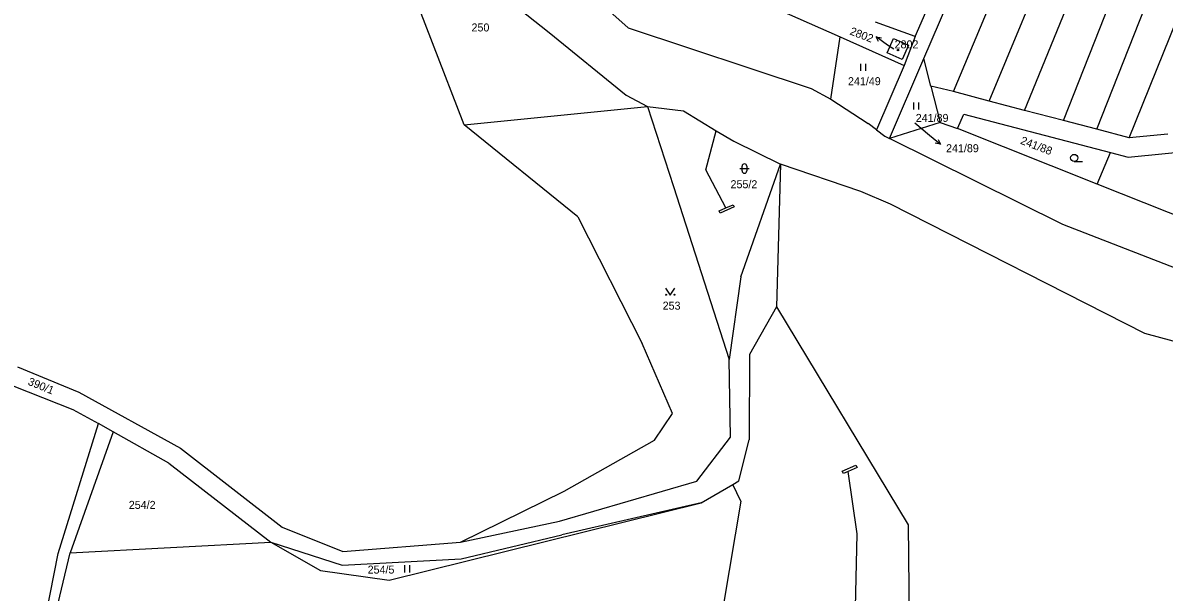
# Model space of a CAD drawing. Extents: x -735249 to -729401, y -1124843 to -1121828.
# Drawn here: x -732832.6 to -732590.1, y -1123273.2 to -1123152.2 of the extents above; entities that cross this region are included whole.
import ezdxf

# ---------------------------------------------------------------- set-up
doc = ezdxf.new("R2010")
doc.units = 0
for name, color, linetype in [('Vrstva 1', 7, 'Continuous'), ('Vrstva 16', 7, 'Continuous'), ('Vrstva 18', 7, 'Continuous'), ('Vrstva 19', 7, 'Continuous'), ('Vrstva 25', 7, 'Continuous'), ('Vrstva 4', 7, 'Continuous')]:
    doc.layers.add(name, color=color, linetype=linetype)

msp = doc.modelspace()

# ---------------------------------------------------------------- linework, layer by layer
at = {"layer": 'Vrstva 1'}
for points in [[(-732642.99, -1123155.08), (-732616.53, -1123094.53)], [(-732641.15, -1123159.81), (-732613.49, -1123095.44)], [(-732634.89, -1123166.81), (-732605.83, -1123097.48)], [(-732627.27, -1123168.84), (-732598.56, -1123099.61)], [(-732619.76, -1123170.81), (-732591.5, -1123101.68)], [(-732611.48, -1123172.98), (-732584.2, -1123103.81)], [(-732604.41, -1123174.82), (-732577.23, -1123105.85)], [(-732597.51, -1123176.63), (-732569.85, -1123108.01)], [(-732703.99, -1123153.23), (-732734.97, -1123125.53)], [(-732750.92, -1123130.28), (-732720.73, -1123154.25)], [(-732738.85, -1123173.87), (-732752.26, -1123138.97)], [(-732691.85, -1123140.6), (-732658.96, -1123155.15)], [(-732642.99, -1123155.08), (-732651.43, -1123152.09)], [(-732720.73, -1123154.25), (-732704.39, -1123167.54)], [(-732703.99, -1123153.23), (-732665.13, -1123166.13)], [(-732660.89, -1123168.41), (-732658.96, -1123155.15)], [(-732658.96, -1123155.15), (-732645.31, -1123161.3)], [(-732648.98, -1123158.61), (-732647.59, -1123155.54)], [(-732647.59, -1123155.54), (-732644.41, -1123156.98)], [(-732642.99, -1123155.08), (-732645.31, -1123161.3)], [(-732645.77, -1123160.02), (-732648.98, -1123158.61)], [(-732644.41, -1123156.98), (-732645.77, -1123160.02)], [(-732645.31, -1123161.3), (-732651.19, -1123174.93)], [(-732648.43, -1123176.76), (-732641.15, -1123159.81)], [(-732639.66, -1123165.64), (-732641.15, -1123159.81)], [(-732665.13, -1123166.13), (-732660.89, -1123168.41)], [(-732634.89, -1123166.81), (-732639.66, -1123165.64)], [(-732639.66, -1123165.64), (-732637.71, -1123173.41)], [(-732704.39, -1123167.54), (-732699.85, -1123169.97)], [(-732660.89, -1123168.41), (-732652.99, -1123173.56)], [(-732627.27, -1123168.84), (-732634.89, -1123166.81)], [(-732619.76, -1123170.81), (-732627.27, -1123168.84)], [(-732738.85, -1123173.87), (-732699.85, -1123169.97)], [(-732699.85, -1123169.97), (-732692.2, -1123170.92)], [(-732699.85, -1123169.97), (-732694.33, -1123186.97)], [(-732692.2, -1123170.92), (-732685.27, -1123175.12)], [(-732611.48, -1123172.98), (-732619.76, -1123170.81)], [(-732714.67, -1123193.4), (-732738.85, -1123173.87)], [(-732651.19, -1123174.93), (-732652.99, -1123173.56)], [(-732637.71, -1123173.41), (-732648.43, -1123176.76)], [(-732637.71, -1123173.41), (-732633.99, -1123174.64)], [(-732633.99, -1123174.64), (-732632.69, -1123171.58)], [(-732632.69, -1123171.58), (-732601.5, -1123179.76)], [(-732604.41, -1123174.82), (-732611.48, -1123172.98)], [(-732685.27, -1123175.12), (-732681.55, -1123177.38)], [(-732651.19, -1123174.93), (-732649.42, -1123176.27)], [(-732649.42, -1123176.27), (-732648.43, -1123176.76)], [(-732604.32, -1123186.52), (-732633.99, -1123174.64)], [(-732597.51, -1123176.63), (-732604.41, -1123174.82)], [(-732589.35, -1123175.83), (-732597.51, -1123176.63)], [(-732681.55, -1123177.38), (-732671.64, -1123182.23)], [(-732611.6, -1123195.08), (-732648.43, -1123176.76)], [(-732597.74, -1123180.77), (-732573.46, -1123178.35)], [(-732604.32, -1123186.52), (-732601.5, -1123179.76)], [(-732601.5, -1123179.76), (-732597.74, -1123180.77)], [(-732680.05, -1123206.15), (-732671.64, -1123182.23)], [(-732671.64, -1123182.23), (-732672.5, -1123212.58)], [(-732654.58, -1123188.08), (-732671.64, -1123182.23)], [(-732694.33, -1123186.97), (-732682.51, -1123223.75)], [(-732648.27, -1123190.76), (-732654.58, -1123188.08)], [(-732574.03, -1123198.55), (-732604.32, -1123186.52)], [(-732594.22, -1123218.22), (-732648.27, -1123190.76)], [(-732714.67, -1123193.4), (-732700.97, -1123220.35)], [(-732547.95, -1123219.75), (-732611.6, -1123195.08)], [(-732680.05, -1123206.15), (-732682.51, -1123223.75)], [(-732672.5, -1123212.58), (-732678.19, -1123222.66)], [(-732672.5, -1123212.58), (-732644.47, -1123258.86)], [(-732546.58, -1123231.15), (-732594.22, -1123218.22)], [(-732694.58, -1123235.22), (-732700.97, -1123220.35)], [(-732682.22, -1123240.25), (-732682.51, -1123223.75)], [(-732678.19, -1123222.66), (-732678.25, -1123240.84)], [(-732841.01, -1123226.88), (-732821.94, -1123234.41)], [(-732833.74, -1123225.29), (-732820.69, -1123230.66)], [(-732820.69, -1123230.66), (-732799.1, -1123242.6)], [(-732821.94, -1123234.41), (-732816.54, -1123237.36)], [(-732698.39, -1123240.88), (-732694.58, -1123235.22)], [(-732825.06, -1123264.97), (-732816.54, -1123237.36)], [(-732813.36, -1123239.14), (-732822.56, -1123264.84)], [(-732813.36, -1123239.14), (-732816.54, -1123237.36)], [(-732801.55, -1123245.76), (-732813.36, -1123239.14)], [(-732717.6, -1123251.75), (-732698.39, -1123240.88)], [(-732689.41, -1123249.59), (-732682.22, -1123240.25)], [(-732680.47, -1123249.53), (-732678.25, -1123240.84)], [(-732799.1, -1123242.6), (-732777.46, -1123259.41)], [(-732801.55, -1123245.76), (-732779.91, -1123262.57)], [(-732718.59, -1123258.08), (-732689.41, -1123249.59)], [(-732688.48, -1123254.23), (-732681.77, -1123250.29)], [(-732681.77, -1123250.29), (-732680.47, -1123249.53)], [(-732680.05, -1123253.87), (-732681.77, -1123250.29)], [(-732739.58, -1123262.57), (-732717.6, -1123251.75)], [(-732680.05, -1123253.87), (-732683.74, -1123275.75)], [(-732754.73, -1123270.65), (-732688.48, -1123254.23)], [(-732688.48, -1123254.23), (-732718.05, -1123261.03)], [(-732739.58, -1123262.57), (-732718.59, -1123258.08)], [(-732777.46, -1123259.41), (-732764.58, -1123264.57)], [(-732739.45, -1123266.11), (-732718.05, -1123261.03)], [(-732644.47, -1123258.86), (-732644.24, -1123285.88)], [(-732822.56, -1123264.84), (-732779.91, -1123262.57)], [(-732779.91, -1123262.57), (-732764.75, -1123267.46)], [(-732779.91, -1123262.57), (-732769.35, -1123268.57)], [(-732764.58, -1123264.57), (-732739.58, -1123262.57)], [(-732827.64, -1123277.95), (-732825.06, -1123264.97)], [(-732825.83, -1123278.77), (-732822.56, -1123264.84)], [(-732764.75, -1123267.46), (-732739.45, -1123266.11)], [(-732769.35, -1123268.57), (-732754.73, -1123270.65)]]:
    msp.add_lwpolyline(points, dxfattribs=at)
at = {"layer": 'Vrstva 16'}
for points in [[(-732647.57, -1123157.83), (-732648.85, -1123156.92)], [(-732643.08, -1123173.46), (-732639.94, -1123176.08)]]:
    msp.add_lwpolyline(points, dxfattribs=at)
at = {"layer": 'Vrstva 25'}
for points in [[(-732648.85, -1123156.92), (-732651.295, -1123155.183)], [(-732650.769, -1123156.17), (-732651.295, -1123155.183), (-732650.19, -1123155.354)], [(-732654.547, -1123162.395), (-732654.547, -1123160.895)], [(-732653.513, -1123162.395), (-732653.513, -1123160.895)], [(-732643.267, -1123170.625), (-732643.267, -1123169.125)], [(-732642.233, -1123170.625), (-732642.233, -1123169.125)], [(-732639.94, -1123176.08), (-732637.639, -1123178.004)], [(-732638.085, -1123176.979), (-732637.639, -1123178.004), (-732638.727, -1123177.746)], [(-732680.28, -1123183.17), (-732678.28, -1123183.17)], [(-732679.78, -1123183.67), (-732679.78, -1123182.67)], [(-732678.78, -1123182.67), (-732678.78, -1123183.67)], [(-732609.22, -1123181.65), (-732607.47, -1123181.65)], [(-732696.03, -1123208.59), (-732695.03, -1123210.09), (-732694.03, -1123208.59)], [(-732751.417, -1123268.985), (-732751.417, -1123267.485)], [(-732750.383, -1123268.985), (-732750.383, -1123267.485)]]:
    msp.add_lwpolyline(points, dxfattribs=at)
for centre, radius in [((-732646.66, -1123157.98), 0.175), ((-732609.22, -1123180.9), 0.75), ((-732695.93, -1123209.99), 0.1), ((-732694.13, -1123209.99), 0.1)]:
    msp.add_circle(centre, radius, dxfattribs=at)
for centre, start, end in [((-732679.28, -1123182.67), 0.10099, 180.00143), ((-732679.28, -1123183.67), 180.10243, 0.00286)]:
    msp.add_arc(centre, 0.5, start, end, dxfattribs=at)
at = {"layer": 'Vrstva 4'}
for points in [[(-732687.46, -1123183.43), (-732685.27, -1123175.12)], [(-732683.24, -1123191.55), (-732687.46, -1123183.43)], [(-732683.24, -1123191.55), (-732681.7, -1123190.88)], [(-732681.7, -1123190.88), (-732681.46, -1123191.34)], [(-732684.68, -1123192.17), (-732683.24, -1123191.55)], [(-732684.45, -1123192.64), (-732684.68, -1123192.17)], [(-732681.46, -1123191.34), (-732684.45, -1123192.64)], [(-732658.48, -1123247.48), (-732655.58, -1123246.18)], [(-732655.58, -1123246.18), (-732655.34, -1123246.72)], [(-732658.22, -1123247.96), (-732658.48, -1123247.48)], [(-732657.23, -1123247.53), (-732658.22, -1123247.96)], [(-732655.34, -1123246.72), (-732657.23, -1123247.53)], [(-732655.35, -1123260.83), (-732657.23, -1123247.53)], [(-732655.86, -1123285.79), (-732655.35, -1123260.83)]]:
    msp.add_lwpolyline(points, dxfattribs=at)

# ---------------------------------------------------------------- texts
at = {"layer": 'Vrstva 16'}
msp.add_text('2802', height=1.7, rotation=339.0027, dxfattribs=at).set_placement((-732657.026, -1123154.628))
msp.add_text('241/89', height=1.7, dxfattribs=at).set_placement((-732636.44, -1123179.7))
at = {"layer": 'Vrstva 18'}
for s, p in [('250', (-732737.26, -1123154.03)), ('241/49', (-732657.28, -1123165.45)), ('241/89', (-732642.88, -1123173.26)), ('255/2', (-732682.23, -1123187.35)), ('253', (-732696.65, -1123213.16)), ('254/2', (-732810.07, -1123255.5)), ('254/5', (-732759.33, -1123269.25))]:
    msp.add_text(s, height=1.7, dxfattribs=at).set_placement(p)
for s, rotation, p in [('241/88', 339.1027, (-732620.782, -1123177.865)), ('390/1', 337.90269, (-732831.65, -1123229.07))]:
    msp.add_text(s, height=1.7, rotation=rotation, dxfattribs=at).set_placement(p)
at = {"layer": 'Vrstva 19'}
msp.add_text('2802', height=1.7, dxfattribs=at).set_placement((-732647.37, -1123157.63))

doc.saveas('drawing.dxf')
